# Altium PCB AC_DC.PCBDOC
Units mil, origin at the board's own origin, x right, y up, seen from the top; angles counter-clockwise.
Board outline 6000 x 4000 mil, 2 copper layers (Top Layer, Bottom Layer); 9 components, 7 nets, 23 pads, 0 vias.
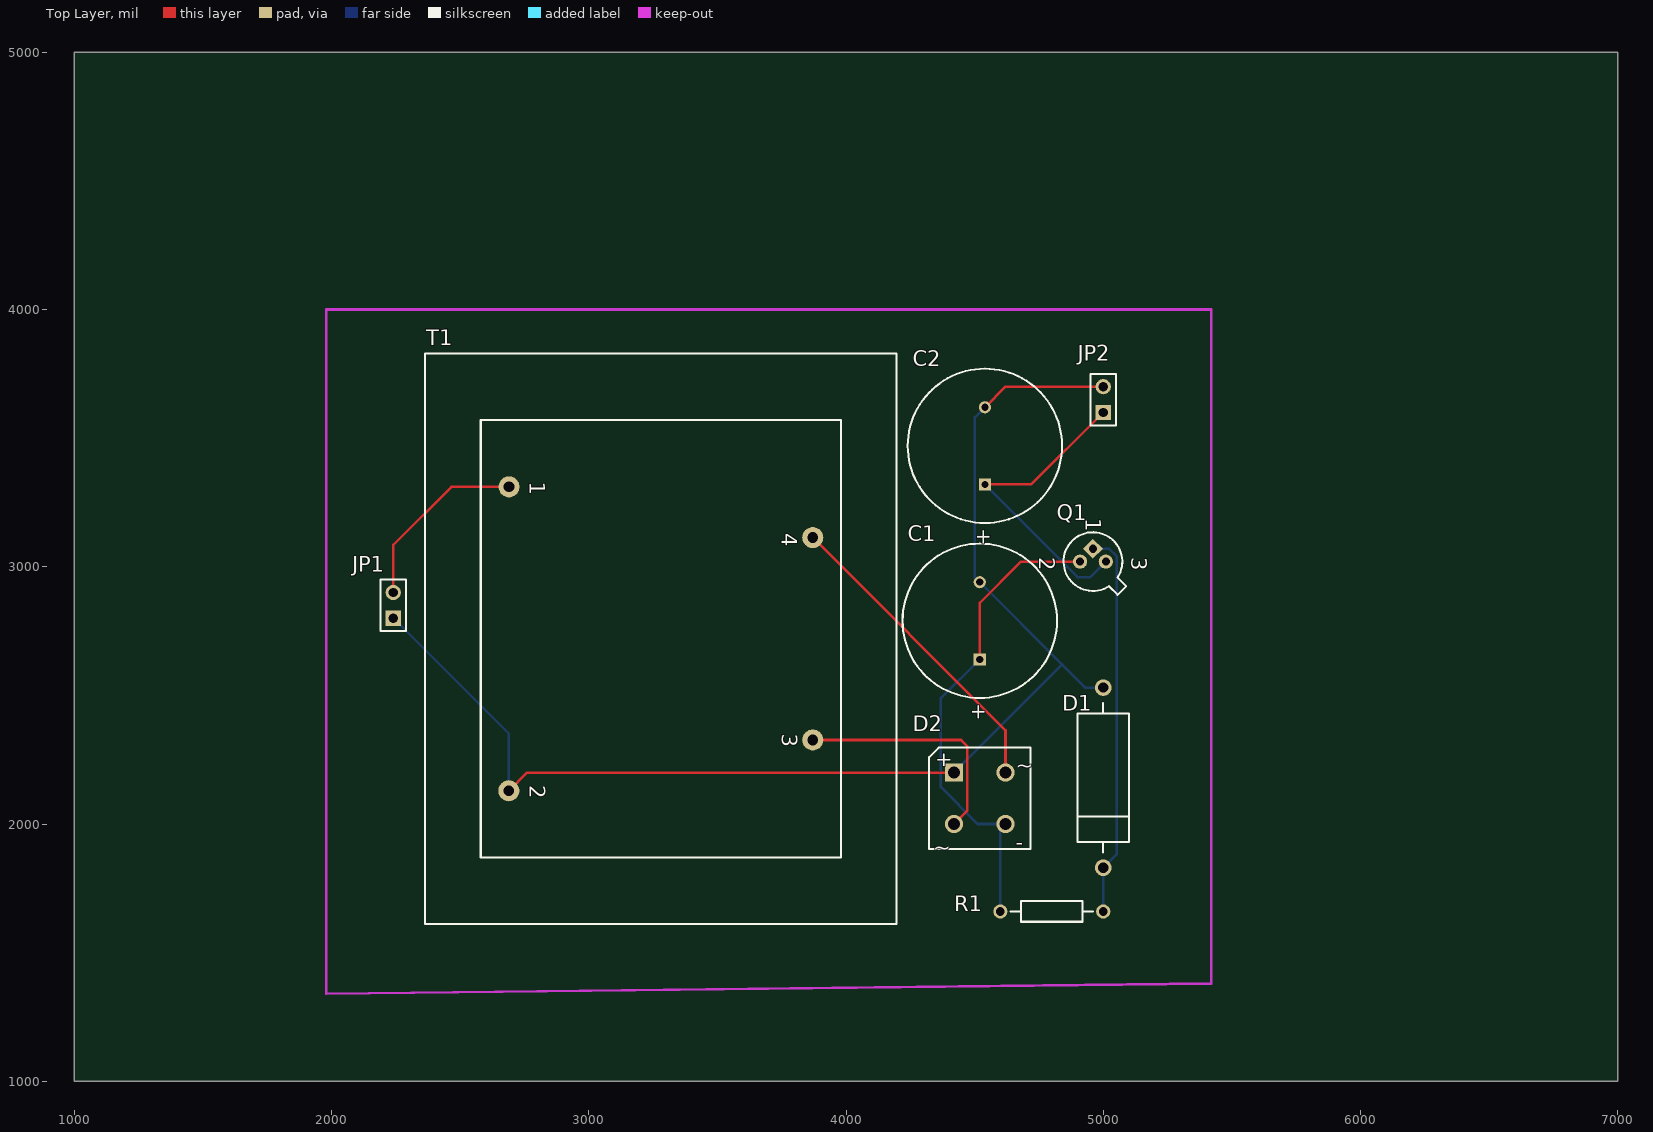
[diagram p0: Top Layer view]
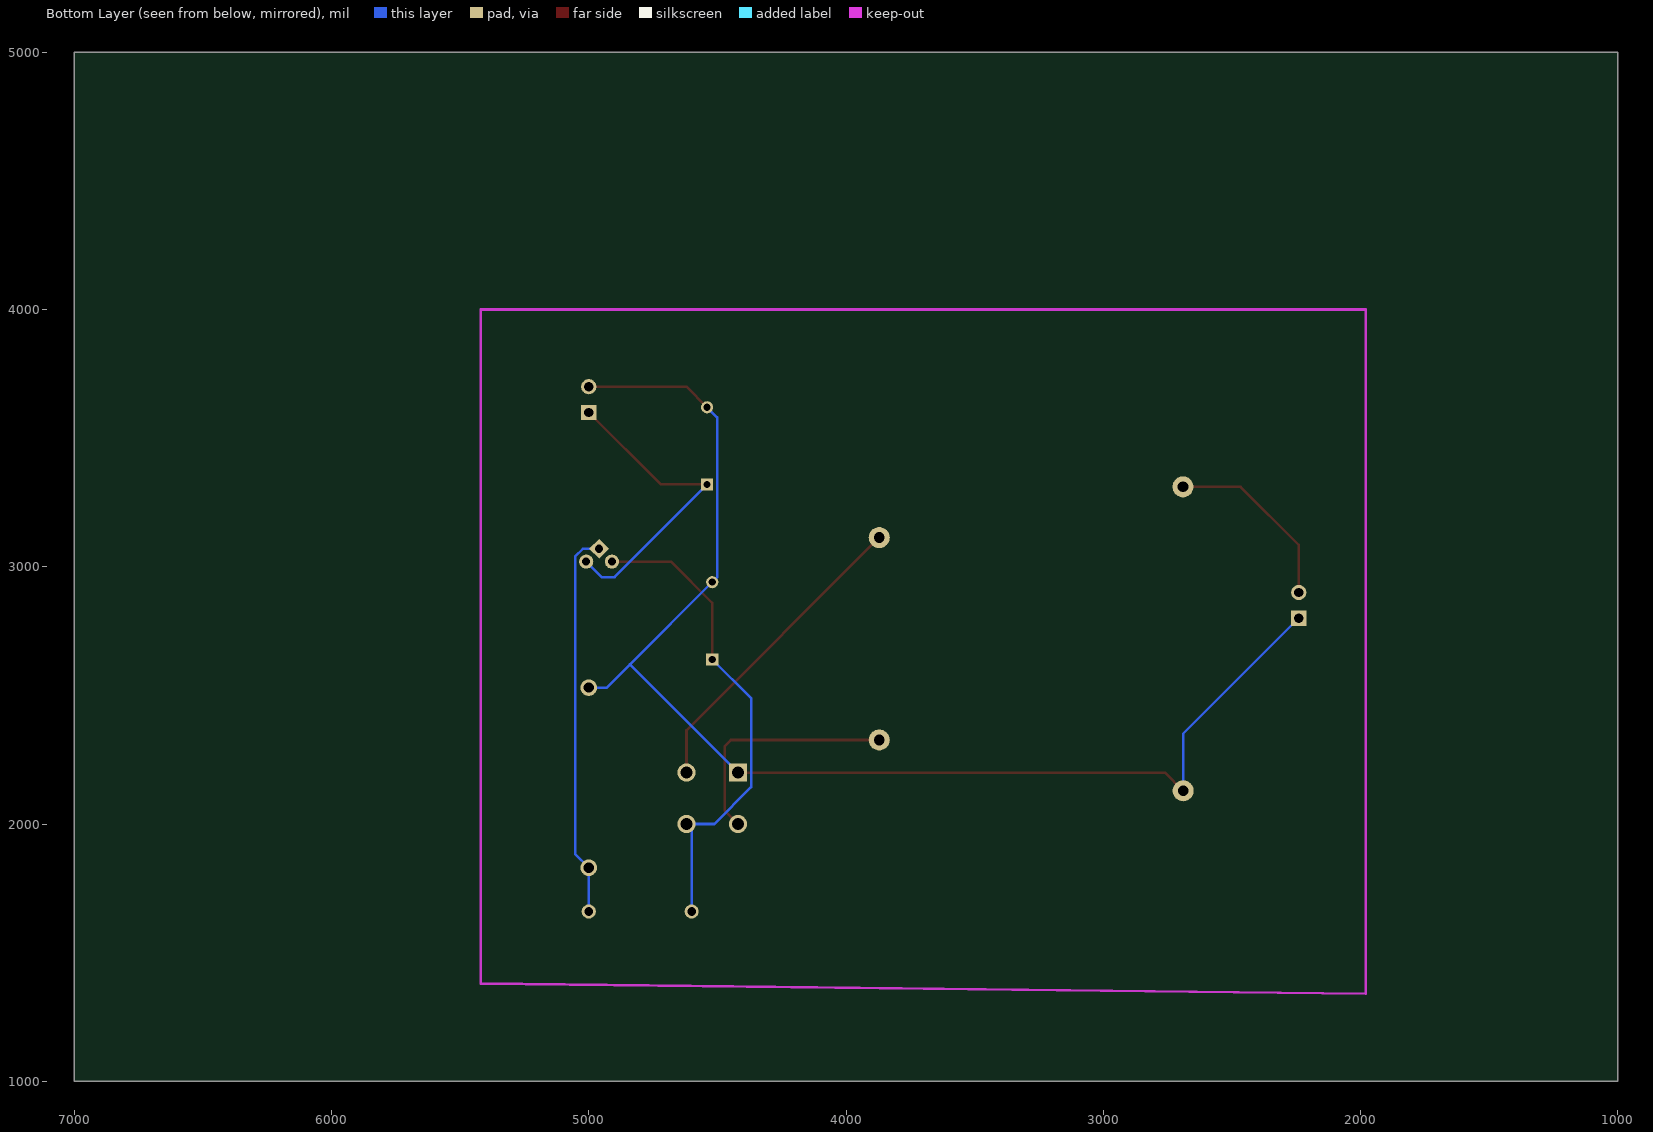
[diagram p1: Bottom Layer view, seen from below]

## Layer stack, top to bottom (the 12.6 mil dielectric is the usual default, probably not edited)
Top Layer: signal copper 1.4
Dielectric: dielectric 12.6, FR-4, Dk 4.8
Bottom Layer: signal copper 1.4

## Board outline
1000,1000 7000,1000 7000,5000 1000,5000

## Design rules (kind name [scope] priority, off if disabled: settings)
Clearance [All] p1: gap=10
ComponentClearance [All] p1: gap=10 collisioncheckmode=0
PolygonConnect [All] p1: connectstyle=Relief reliefconductorwidth=10 reliefentries=4 polygonreliefangle="90 Angle"
RoutingLayers [All] p1: top layer=Horizontal bottom layer=Vertical
RoutingVias [All] p1: holewidth=28 width=50 viastyle="Through Hole" minholewidth=28 minwidth=50 maxholewidth=28 maxwidth=50
SolderMaskExpansion [All] p1: expansion=4
TestPointUsage [All] p1: valid=0 allowmultiple=FALSE
Testpoint [All] p1: side=15 testpointundercomponent=TRUE minsize=40 maxsize=100 preferedsize=60 minholesize=0 maxholesize=40 preferedholesize=32 testpointgrid=1 style=1023 order=-539222988
Width [All] p1: maxlimit=10 minlimit=10 preferedwidth=10
16 further rules are at their usual default settings.

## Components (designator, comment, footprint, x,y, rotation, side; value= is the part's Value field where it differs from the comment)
C1 "Cap Pol1" RB7.6-15 4520,2640 r270 top
C2 "Cap Pol1" RB7.6-15 4540,3320 r270 top
D1 "D Zener" DIODE-0.7 5000,2180 r270 top
D2 "Bridge1" E-BIP-P4/D10 4520,2100 r0 top
JP1 "Header 2" HDR1X2 2240,2800 r90 top
JP2 "Header 2" HDR1X2 5000,3600 r90 top
Q1 "2N2222A" CAN-3/D5.8 4960,3020 r270 top
R1 "680" AXIAL-0.4 4800,1660 r180 top
T1 "Trans Ideal" TRF_4 3280,2720 r270 top

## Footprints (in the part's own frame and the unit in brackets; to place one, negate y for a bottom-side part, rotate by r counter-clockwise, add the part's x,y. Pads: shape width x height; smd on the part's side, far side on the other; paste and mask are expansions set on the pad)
AXIAL-0.4 [mm]
  round 1.4 hole 0.85: 1(-5.08,0) 2(5.08,0)
  silkscreen extent -4.06,-1.02 4.06,1.02
CAN-3/D5.8 [mm]
  rect 1.4x1.4 hole 0.8 rot 45: 1(-1.27,0)
  round 1.4 hole 0.8: 2(0,-1.27) 3(0,1.27)
  silkscreen extent -2.9,-2.9 3.28,3.28
DIODE-0.7 [mm]
  round 1.65 hole 1: 1(-8.89,0) 2(8.89,0)
  silkscreen extent -7.37,-2.54 7.37,2.54
E-BIP-P4/D10 [mm]
  rect 1.8x1.8 hole 1.2: 1(-2.54,2.54)
  round 1.8 hole 1.2: 2(-2.54,-2.54) 3(2.54,-2.54) 4(2.54,2.54)
  silkscreen extent -5,-5 5,5
HDR1X2 [mm]
  rect 1.5x1.5 hole 0.9: 1(0,0)
  round 1.5 hole 0.9: 2(2.54,0)
  silkscreen extent -1.27,-1.27 3.81,1.27
RB7.6-15 [mm]
  rect 1.2x1.2 hole 0.7: 1(0,0)
  round 1.2 hole 0.7: 2(-7.62,0)
  silkscreen extent -11.43,-7.62 3.81,7.62
TRF_4 [mil]
  round 82 hole 42: 1(-590.83,-590) 2(590.83,-590.83) 3(393.33,590.83) 4(-393.33,590.83)
  silkscreen extent -1108,-917 1108,917

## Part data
C1 C2: "Polarized Capacitor (Radial)"
D1: "Zener Diode"
D2: "Full Wave Diode Bridge"
JP1 JP2: "Header, 2-Pin"
Q1: "High Speed Switches"
R1: library part Res2, "Resistor"
T1: "Transformer (Ideal)"

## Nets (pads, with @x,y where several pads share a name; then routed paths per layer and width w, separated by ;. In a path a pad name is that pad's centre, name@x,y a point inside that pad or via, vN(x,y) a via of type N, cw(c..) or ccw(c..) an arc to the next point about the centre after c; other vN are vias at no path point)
GND: C1.2 C2.2 D1.1 D2.1 JP1.1 JP2.2 T1.2 | length 5058
  Top Layer w10: T1.2 2760,2200 D2.1 ; C2.2 4620,3700 JP2.2
  Bottom Layer w10: JP1.1 2689.17,2350.83 T1.2 ; D2.1 4840,2620 ; C2.2 4501,3581 4501,2959 C1.2 4840,2620 ; D1.1 4930,2530 4840,2620
NetC1_1: C1.1 D2.3 Q1.2 R1.2 | length 1886.1
  Top Layer w10: C1.1 4520,2860 4680,3020 Q1.2
  Bottom Layer w10: C1.1 4369,2489 4369,2143 4512,2000 D2.3@4600,2000 ; R1.2 D2.3@4600,2000 ; D2.3 D2.3@4600,2000
NetC2_1: C2.1 JP2.1 Q1.3 | length 1219.9
  Top Layer w10: C2.1 4720,3320 JP2.1
  Bottom Layer w10: C2.1 4900,2960 4950,2960 Q1.3
NetD1_2: D1.2 Q1.1 R1.1 | length 1507.4
  Bottom Layer w10: Q1.1 5023,3070 5053,3040 5053,1883 D1.2 R1.1
NetD2_2: D2.2 T1.3 | length 934.1
  Top Layer w10: T1.3 4447.33,2326.67 4471,2303 4471,2051 D2.2
NetD2_4: D2.4 T1.4 | length 1223.6
  Top Layer w10: T1.4 4620,2364.17 D2.4
NetJP1_2: JP1.2 T1.1 | length 728.5
  Top Layer w10: JP1.2 2240,3085 2465.83,3310.83 T1.1

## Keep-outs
Keep-Out Layer:
  lines w10: 1980,1340 1980,3640 1980,4000 5420,4000 5420,1380 1980,1340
